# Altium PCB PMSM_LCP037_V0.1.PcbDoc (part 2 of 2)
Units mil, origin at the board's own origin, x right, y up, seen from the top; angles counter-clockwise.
Board outline 6102.36 x 5157.48 mil, 2 copper layers (Top Layer, Bottom Layer); 106 components, 56 nets, 276 pads, 861 vias.
Unrouted connection lines stored in the file: 2.
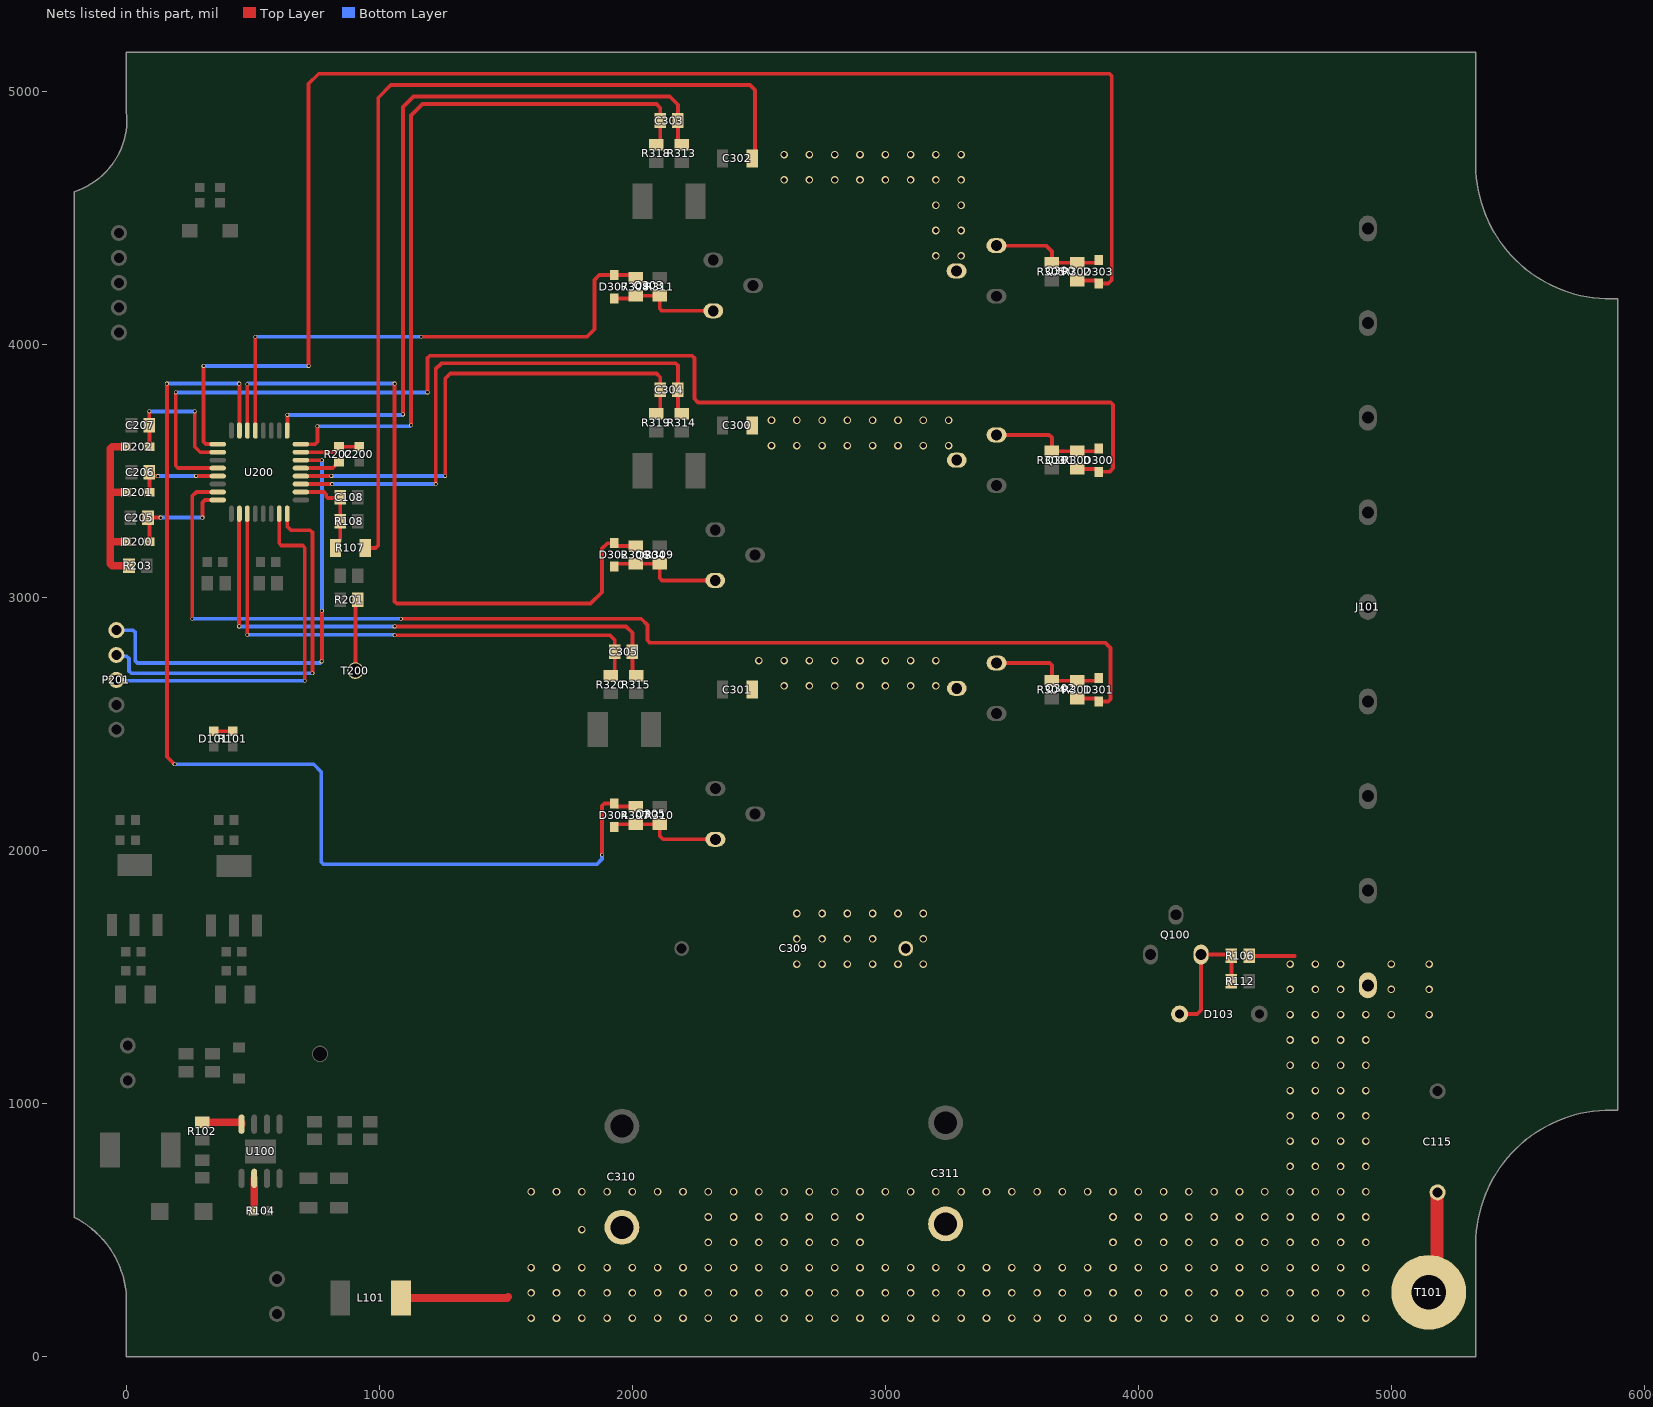
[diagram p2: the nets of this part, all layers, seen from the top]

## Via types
v1: diameter 30, hole 20, Top Layer to Bottom Layer, 742 vias
v2: diameter 15, hole 10, Top Layer to Bottom Layer, 100 vias
v3: diameter 30, hole 15, Top Layer to Bottom Layer, 14 vias
v4: diameter 24, hole 12, Top Layer to Bottom Layer, 4 vias
v5: diameter 20, hole 10, Top Layer to Bottom Layer, 1 vias

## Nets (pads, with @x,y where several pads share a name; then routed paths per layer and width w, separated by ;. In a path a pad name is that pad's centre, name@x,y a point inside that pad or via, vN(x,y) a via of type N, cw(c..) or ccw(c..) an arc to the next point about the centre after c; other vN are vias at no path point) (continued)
NetC200_2: C200.2 R202.1 U200.15 | length 239.6
  Top Layer w15: U200.15@689.37,3573.74 817.44,3573.74 839.02,3595.31 R202.1@840,3595.31 C200.2@920,3595.32
NetD101_A: D101.A R101.1 | length 75
  Top Layer w15: D101.A@345,2470.32 R101.1@420,2470.31
NetD103_2: D103.2 Q100.1 R106.1 R112.2 | length 530.3
  Top Layer w15: D103.2@4163.35,1352.52 4233.31,1352.52 4248.31,1367.52 Q100.1@4248.31,1587.52 4358.31,1587.52 R106.1@4363.31,1592.52 ; R106.1@4368.27,1582.52 4368.27,1487.56 R112.2@4373.31,1482.52
NetD200_1: D200.1 D201.1 D202.1 R203.2 | length 731.8
  Top Layer w30: D201.1@-1.57,3415 -57.5,3415 -65,3407.5 ; D202.1@-1.57,3595 -56.21,3595 -65,3586.21 -65,3407.5 ; D200.1@-1.46,3220 -56.21,3220 -65,3228.79 ; R203.2@9.96,3125 -56.21,3125 -65,3133.79 -65,3228.79 ; -65,3228.79 -65,3407.5
NetD300_1: D300.1 Q301.1 R300.2 R303.2 | length 467.9
  Top Layer w15: Q301.1@3439.8,3642.2 3647.32,3642.2 3658.31,3631.21 R303.2@3658.31,3577.56 R300.2@3758.31,3577.6 R300.2@3758.31,3577.6 3834.47,3577.6 3843.31,3586.44 D300.1@3843.31,3588.98
NetD301_1: D301.1 Q302.1 R301.2 R304.2 | length 474.7
  Top Layer w15: Q302.1@3439.8,2740.24 3440.04,2740 3649.52,2740 3658.31,2731.21 R304.2@3658.31,2670.04 R301.2@3758.31,2670.04 3834.47,2670.04 3843.31,2678.88 D301.1@3843.31,2681.46
NetD302_1: D302.1 Q304.1 R306.2 R309.2 | length 465.9
  Top Layer w15: D302.1@1928.31,3121.06 1928.31,3123.64 1937.15,3132.48 R306.2@2013.31,3132.48 R309.2@2108.31,3132.48 2108.31,3075.79 2117.09,3067.01 Q304.1@2327.6,3067.01
NetD303_1: D303.1 Q300.1 R302.2 R305.2 | length 464.4
  Top Layer w15: Q300.1@3439.02,4390.24 3634.76,4390.24 3658.31,4366.69 R305.2@3658.31,4322.56 R302.2@3758.31,4322.56 3834.47,4322.56 3843.31,4331.4 D303.1@3843.31,4333.98
NetD304_1: D304.1 Q305.1 R307.2 R310.2 | length 457.2
  Top Layer w15: D304.1@1928.31,2091.06 1928.31,2093.64 1937.15,2102.48 R307.2@2013.31,2102.48 R310.2@2108.31,2102.48 2108.31,2056.69 2121.61,2043.39 Q305.1@2327.99,2043.39
NetD307_1: D307.1 Q303.1 R308.2 R311.2 | length 459.3
  Top Layer w15: D307.1@1923.31,4192.52 1934.76,4181.06 2001.89,4181.06 R308.2@2013.31,4192.48 R308.2@2013.31,4192.48 R311.2@2108.31,4192.48 2108.31,4141.31 2117.09,4132.52 Q303.1@2318.31,4132.52
NetR102_2: R102.2 U100.8 | length 161.1
  Top Layer w30: R102.2@300,925.04 451.85,925.04 455,921.89 U100.8@455,917.11
NetR104_1: R104.1 U100.2 | length 130.1
  Top Layer w30: R104.1@499.69,575 499.69,575.98 505,581.3 U100.2@505,702.89
NetR201_1: R201.1 T200.1 | length 284.2
  Top Layer w15: T200.1@905,2710 905,2979.96 R201.1@915.04,2990
NetR202_2: R202.2 U200.13 | length 160.5
  Top Layer w15: U200.13@689.37,3510.75 815.08,3510.75 839.02,3534.68 R202.2@840,3534.68
OPA0N: C303.1 R318.1 U200.16 | length 2888.3
  Top Layer w15: U200.16@689.37,3605.24 745,3605.24 755,3615.24 v2(755,3676.21) ; v2(1125,3680) 1125,4905 1170,4950 2095,4950 2109.96,4935.04 C303.1@2109.96,4885 2109.96,4805 R318.1@2095,4790.04
  Bottom Layer w15: v2(755,3676.21) 1121.21,3676.21 v2(1125,3680)
OPA0P: C303.2 R313.1 U200.17 | length 3016.3
  Top Layer w15: U200.17@635.24,3659.37 635.98,3660.12 v2(635.98,3720.98) ; v2(1092.99,3722.99) 1092.99,4937.99 1135,4980 2147.42,4980 2180.04,4947.38 C303.2@2180.04,4885 2180.04,4805 R313.1@2195,4790.04
  Bottom Layer w15: v2(635.98,3720.98) 1090.98,3720.98 v2(1092.99,3722.99)
OPA1N: C305.1 R320.1 U200.3 | length 2086.7
  Top Layer w15: U200.3@477.76,3330.63 477.76,2852.24 v2(478.32,2851.68) ; v2(1060,2850) 1911.17,2850 1929.96,2831.21 C305.1@1929.96,2785 1929.96,2705 R320.1@1915,2690.04
  Bottom Layer w15: v2(478.32,2851.68) 1058.32,2851.68 v2(1060,2850)
OPA1P: C305.2 R315.1 U200.2 | length 2187.7
  Top Layer w15: v2(445,2885) 445,3329.37 U200.2@446.26,3330.63 ; v2(1060,2885) 1975,2885 2000.04,2859.96 C305.2@2000.04,2785 2000.04,2705 R315.1@2015,2690.04
  Bottom Layer w15: v2(445,2885) v2(1060,2885)
OPA2N: C304.1 R319.1 U200.12 | length 1971.3
  Top Layer w15: U200.12@689.37,3479.25 v2@810,3479.25 ; v2(1260,3480) 1260,3865 1280,3885 2095,3885 2109.96,3870.04 C304.1@2109.96,3820 2109.96,3740 R319.1@2095,3725.04
  Bottom Layer w15: v2(810,3480) v2(1260,3480)
OPA2P: C304.2 R314.1 U200.11 | length 2155.6
  Top Layer w15: U200.11@689.37,3447.76 v2(812.76,3447.76) ; v2(1222.24,3447.76) 1222.24,3902.24 1245,3925 2171.25,3925 2180.04,3916.21 C304.2@2180.04,3820 2180.04,3740 R314.1@2195,3725.04
  Bottom Layer w15: v2(812.76,3447.76) v2(1222.24,3447.76)
PA0-DIO: P201.3 U200.7 | length 1498
  Top Layer w15: U200.7@603.74,3330.63 603.74,3213.79 612.53,3205 696.21,3205 705,3196.21 v2(705,2670)
  Bottom Layer w15: P201.3@-40,2673.43 -36.57,2670 v2(705,2670)
PA1-CLK: P201.2 U200.8 | length 1550.1
  Top Layer w15: U200.8@635.24,3330.63 635.24,3279.76 650,3265 726.21,3265 735,3256.21 v2(735,2700)
  Bottom Layer w15: P201.2@-40,2771.85 -34.85,2766.7 1.21,2766.7 10,2757.92 10,2708.79 18.79,2700 v2(735,2700)
PB0-STB: P201.1 U200.14 | length 1815.6
  Top Layer w15: U200.14@689.37,3542.24 v2(772.76,3542.24) ; v2@770,2745 v2(771.38,2746.38) 772.76,2747.76 v2(772.76,2947.24)
  Bottom Layer w15: P201.1@-40,2870.28 -39.72,2870 26.21,2870 35,2861.21 35,2748.79 43.79,2740 765,2740 v2(771.38,2746.38) ; v2(772.76,2947.24) v2(772.76,3542.24)
PE: C115.2 T101.6 | length 409.5
  Top Layer w50: T101.6@5148.31,252.52 5180.82,285.03 5180.82,645.03 C115.2@5183.31,647.52
POWER: C300.2 C301.2 C302.2 C309.2 C310.1 C311.1 J101.1 L101.1 Q300.2 Q301.2 Q302.2 R106.2 R107.2 | length 4226.2
  Top Layer w15: R107.2@943.66,3195 985,3195 995,3205 995,4975 1045,5025 2465,5025 2485,5005 2485,4746.34 C302.2@2473.66,4735 ; R106.2@4438.35,1582.52 4618.31,1582.52
  Top Layer w30: L101.1@1085,230 1505,230 1510,235
  other v1: 1600,150 1700,150 1800,150 1900,150 2000,150 2100,150 2200,150 2300,150 2400,150 2500,150 2600,150 2700,150 2800,150 2900,150 3000,150 3100,150 3200,150 3300,150 3400,150 3500,150 3600,150 3700,150 3800,150 3900,150 4000,150 4100,150 4200,150 4300,150 4400,150 4500,150 4600,150 4700,150 4800,150 4900,150 1600,250 1700,250 1800,250 1900,250 2000,250 2100,250 2200,250 2300,250 2400,250 2500,250 2600,250 2700,250 2800,250 2900,250 3000,250 3100,250 3200,250 3300,250 3400,250 3500,250 3600,250 3700,250 3800,250 3900,250 4000,250 4100,250 4200,250 4300,250 4400,250 4500,250 4600,250 4700,250 4800,250 4900,250 1600,350 1700,350 1800,350 1900,350 2000,350 2100,350 2200,350 2300,350 2400,350 2500,350 2600,350 2700,350 2800,350 2900,350 3000,350 3100,350 3200,350 3300,350 3400,350 3500,350 3600,350 3700,350 3800,350 3900,350 4000,350 4100,350 4200,350 4300,350 4400,350 4500,350 4600,350 4700,350 4800,350 4900,350 2300,450 2400,450 2500,450 2600,450 2700,450 2800,450 2900,450 3900,450 4000,450 4100,450 4200,450 4300,450 4400,450 4500,450 4600,450 4700,450 4800,450 4900,450 1800,500 2300,550 2400,550 2500,550 2600,550 2700,550 2800,550 2900,550 3900,550 4000,550 4100,550 4200,550 4300,550 4400,550 4500,550 4600,550 4700,550 4800,550 4900,550 1600,650 1700,650 1800,650 1900,650 2000,650 2100,650 2200,650 2300,650 2400,650 2500,650 2600,650 2700,650 2800,650 2900,650 3000,650 3100,650 3200,650 3300,650 3400,650 3500,650 3600,650 3700,650 3800,650 3900,650 4000,650 4100,650 4200,650 4300,650 4400,650 4500,650 4600,650 4700,650 4800,650 4900,650 4600,750 4700,750 4800,750 4900,750 4600,850 4700,850 4800,850 4900,850 4600,950 4700,950 4800,950 4900,950 4600,1050 4700,1050 4800,1050 4900,1050 4600,1150 4700,1150 4800,1150 4900,1150 4600,1250 4700,1250 4800,1250 4900,1250 4600,1350 4700,1350 4800,1350 4900,1350 5000,1350 5150,1350 4600,1450 4700,1450 4800,1450 5000,1450 5150,1450 2650,1550 2750,1550 2850,1550 2950,1550 3050,1550 3150,1550 4600,1550 4700,1550 4800,1550 5000,1550 5150,1550 2650,1650 2750,1650 2850,1650 2950,1650 3150,1650 2650,1750 2750,1750 2850,1750 2950,1750 3050,1750 3150,1750 2600,2650 2700,2650 2800,2650 2900,2650 3000,2650 3100,2650 3200,2650 2500,2750 2600,2750 2700,2750 2800,2750 2900,2750 3000,2750 3100,2750 3200,2750 2550,3600 2650,3600 2750,3600 2850,3600 2950,3600 3050,3600 3150,3600 3250,3600 2550,3700 2650,3700 2750,3700 2850,3700 2950,3700 3050,3700 3150,3700 3250,3700 3200,4350 3300,4350 3200,4450 3300,4450 3200,4550 3300,4550 2600,4650 2700,4650 2800,4650 2900,4650 3000,4650 3100,4650 3200,4650 3300,4650 2600,4750 2700,4750 2800,4750 2900,4750 3000,4750 3100,4750 3200,4750 3300,4750
UH: D303.2 R302.1 U200.25 | length 6039.8
  Top Layer w15: v2(305,3915) 305,3615 314.02,3605.98 359.88,3605.98 U200.25@360.63,3605.24 ; v2(720,3915) 720,5030 760,5070 3886.21,5070 3895,5061.21 3895,4255 3881.06,4241.06 D303.2@3843.31,4241.06 3843.31,4243.64 3834.47,4252.48 R302.1@3758.31,4252.48
  Bottom Layer w15: v2(305,3915) v2(720,3915)
UL: D307.2 R308.1 U200.21 | length 2088.2
  Top Layer w15: U200.21@509.25,3659.37 v2(509.25,4030) ; v2(1165,4030) 1820,4030 1850,4060 1850,4255 1868.98,4273.98 D307.2@1928.31,4273.98 ; D307.2@1934.76,4273.98 2001.89,4273.98 R308.1@2013.31,4262.56
  Bottom Layer w15: v2(509.25,4030) v2(1165,4030)
VB-U: C205.2 D200.2 U200.32 | length 437.2
  Top Layer w15: D200.2@91.46,3220 91.46,3308.58 C205.2@85.04,3315 v2(135,3315) ; v2(300,3315) 300,3374.76 310,3384.76 U200.32@360.63,3384.76
  Bottom Layer w15: v2(135,3315) v2(300,3315)
VB-V: C206.2 D201.2 U200.29 | length 356
  Top Layer w15: C206.2@89.92,3495 91.34,3493.58 C206.2@91.34,3493.17 ; D201.2@91.34,3415 C206.2@91.34,3493.17 ; v2(124.57,3479.25) 105.26,3479.25 C206.2@91.34,3493.17 ; v2@275,3479.25 U200.29@360.63,3479.25
  Bottom Layer w15: v2(124.57,3479.25) 274.25,3479.25 v2(275,3480)
VB-W: C207.2 D202.2 U200.26 | length 560.1
  Top Layer w15: v2(90,3735) 89.92,3734.92 C207.2@89.92,3680 91.34,3678.58 D202.2@91.34,3595 ; v2(270,3735) 270,3595 291.26,3573.74 U200.26@360.63,3573.74
  Bottom Layer w15: v2(90,3735) v2(270,3735)
Vdect: C108.2 R107.1 R108.2 U200.10 | length 379.1
  Top Layer w15: U200.10@689.37,3416.26 781.21,3416.26 790,3407.47 790,3398.79 796.14,3392.64 842.61,3392.64 C108.2@844.96,3395 R108.2@844.96,3300 844.96,3226.81 826.34,3208.19 R107.1@826.34,3195
VH: D300.2 R300.1 U200.28 | length 4884
  Top Layer w15: v2(195,3810) 195,3520 204.25,3510.75 U200.28@360.63,3510.75 ; v2(1190,3810) 1190,3946.21 1198.79,3955 2236.21,3955 2245,3946.21 2245,3785 2260,3770 3891.21,3770 3900,3761.21 3900,3510 3886.06,3496.06 D300.2@3843.31,3496.06 3843.31,3498.68 3834.47,3507.52 R300.1@3758.31,3507.52
  Bottom Layer w15: v2(195,3810) v2(1190,3810)
VL: D302.2 R306.1 U200.22 | length 2790.9
  Top Layer w15: U200.22@477.76,3659.37 v2(477.76,3842.24) ; v2(1060,3845) 1060,2983.79 1068.79,2975 1835,2975 1880,3020 1880,3192.83 1901.14,3213.98 D302.2@1928.31,3213.98 1928.31,3211.4 1937.15,3202.56 R306.1@2013.31,3202.56
  Bottom Layer w15: v2(477.76,3842.24) 480.51,3845 v2(1060,3845)
WH: D301.2 R301.1 U200.31 | length 4649.4
  Top Layer w15: v2(260,2915) 260,3400 276.26,3416.26 U200.31@360.63,3416.26 ; v2(1085,2915) 2035,2915 2060,2890 2060,2830 2070,2820 3870,2820 3890,2800 3890,2597.33 3881.21,2588.54 D301.2@3843.31,2588.54 3843.31,2591.12 3834.47,2599.96 R301.1@3758.31,2599.96
  Bottom Layer w15: v2(260,2915) v2(1085,2915)
WL: D304.2 R307.1 U200.23 | length 4413.4
  Top Layer w15: v2(160,3845) 160,2370 v2(190,2340) ; U200.23@446.26,3659.37 v2@446.26,3845 ; v2(1880,1982.28) 1880,2176.21 1888.79,2185 1927.28,2185 D304.2@1928.31,2183.98 1928.31,2181.4 1937.15,2172.56 R307.1@2013.31,2172.56
  Bottom Layer w15: v2(160,3845) v2(445,3845) ; v2(190,2340) 740,2340 770,2310 770,1953.79 778.79,1945 1860,1945 1880,1965 v2(1880,1982.28)
pads on no net: J101.6 J101.7 J101.8 J101.9 Q300. Q301. Q302. Q303. Q304. Q305. U100.6 U100.7 U100.9
copper on no net:
  other v4: 510.32,790.31 549.69,790.31 510.32,829.68 549.69,829.68

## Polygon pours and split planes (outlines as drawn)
POWER on Top Layer "POWER_L01_P109" (solid, remove dead copper, pour order 109): 3190,1775 3200,1765 3200,1470 3170,1440 2575,1440 2550,1465 2550,1760 2565,1775
DGND on Top Layer "DGND_L01_P108" (solid, remove dead copper, pour order 108): 1070,2805 1830,2805 1850,2785 1850,2645 1855,2640 1945,2640 1955,2630 1955,2250 1935,2230 1130,2230 1060,2300 1060,2795
DGND on Top Layer "DGND_L01_P107" (solid, remove dead copper, pour order 107): 1941.46,2578.54 1940,2580 1870,2580 1845,2605 1845,2790 1070,2805 1005,2735 1005,2640 955,2590 830,2590 810,2570 810,1245 825,1230 825,1090 835,1080 990,1080 1125,945 1125,865 1180,810 3680,810 3725,855 3725,1115 3915,1305 4095,1305 4110,1320 4110,1390 4135,1415 4170,1415 4195,1440 4195,1640 4180,1655 4045,1655 4030,1670 4030,1780 4010,1800 3260,1800 3235,1775 3235,1450 3170,1385 2555,1385 2520,1420 2520,1750 2470,1800 1865,1800 1835,1830 1835,2220 1845,2230 1935,2230 1950,2245 1950,2570 1940,2580 1870,2580 1845,2605 1845,2790 1830,2790 1070,2800
DGND on Top Layer "DGND_L01_P105" (solid, remove dead copper, pour order 105): 4151.33,1649.5 4035.5,1649.5 4015,1670 4015,1775 4000,1790 3260,1790 3255,1785 3255,1444.21 3198.31,1387.52 977.52,1387.52 945,1355 945,1125 1262.48,807.52 3643.31,807.52 3688.31,852.52 3688.31,1073.31 3917.52,1302.52 4107.52,1302.52 4110,1305 4110,1390 4135,1415 4170,1415 4190,1435 4190,1640 4180,1650 4151.83,1650
POWER on Top Layer "POWER_L01_P088" (solid, remove dead copper, pour order 88): 2435,2760 2435,2585 2475.46,2544.54 3319.51,2544.54 3330,2555.03 3330,2775 3315,2790 2465,2790
ISENCE on Top Layer "ISENCE_L01_P087" (solid, remove dead copper, pour order 87): 2400,2550 2400,2725 2385,2740 2110,2740 2080,2710 2080,2525 2375,2525
POWER on Top Layer "POWER_L01_P086" (solid, remove dead copper, pour order 86): 2440,3585 2460,3565 3185,3565 3205,3545 3205,3505 3225,3485 3330,3485 3355,3510 3355,3725 3340,3740 2445,3740 2440,3735
IV on Top Layer "IV_L01_P085" (solid, remove dead copper, pour order 85): 2417.87,3594.25 2417.87,3737.13 2405,3750 2260,3750 2255,3745 2255,3600 2265,3590 2413.62,3590
POWER on Top Layer "POWER_L01_P084" (solid, remove dead copper, pour order 84): 2440,4795 2455,4810 3345,4810 3375,4780 3375,4275 3350,4250 3180,4250 3150,4280 3150,4545 3091.18,4603.82 2466.18,4603.82 2440,4630
IU on Top Layer "IU_L01_P083" (solid, remove dead copper, pour order 83): 2410,4660 2410,4805 2405,4810 2270,4810 2265,4805 2265,4670 2275,4660
DGND on Top Layer "DGND_L01_P081" (solid, remove dead copper, pour order 81): 990,4700 1020,4670 1020,2795 980,2755 800,2755 770,2725 770,2010 735,1975 220,1975 110,2085 110,2965 60,3015 -105,3015 -150,3060 -150,4545 5,4700
DGND on Top Layer "DGND_L01_P079" (solid, remove dead copper, pour order 79): 970,1000 1050,920 1050,85 1015,50 440,50 420,70 420,415 350,485 40,485 -130,655 -130,975 -105,1000
no net on Top Layer "NONET_L01_P072" (solid, pour order 72): 1170,2990
ISENCE on Top Layer "ISENCE_L01_P069" (solid, remove dead copper, pour order 69): 1325,3690 2130,3690 2160,3660 2160,3305 2150,3295 2100,3295 2090,3285 2090,3260 2075,3245 1320,3245 1300,3265 1300,3665
ISENCE on Top Layer "ISENCE_L01_P067" (solid, remove dead copper, pour order 67): 1345,4755 2150,4755 2160,4745 2160,4370 2150,4360 2100,4360 2090,4350 2090,4325 2070,4305 1345,4305 1300,4350 1300,4710
ISENCE on Top Layer "ISENCE_L01_P066" (solid, remove dead copper, pour order 66): 2390,2560 2400,2550 2400,2135 2385,2120 2185,2120 2160,2145 2160,2280 2150,2290 2000,2290 1985,2305 1985,2550 1995,2560
IV on Top Layer "IV_L01_P065" (solid, remove dead copper, pour order 65): 2187.87,3594.25 2202.87,3609.25 2390.75,3609.25 2400,3600 2400,3200 2359.25,3159.25 2217.87,3159.25 2187.87,3189.25
DGND on Top Layer "DGND_L01_P064" (solid, remove dead copper, pour order 64): 980,1800 980,1195 2510,1195 2510,1760 2470,1800
MOTOR-C on Top Layer "MOTOR-C_L01_P062" (solid, remove dead copper, pour order 62): 2435,2465 2460,2490 3310,2490 3350,2530 3350,2595 3385,2630 3585,2630 3600,2615 3600,2450.51 3630.51,2420 3975,2420 4030,2365 5170,2365 5230,2305 5230,2095 5190,2055 4000,2055 3960,2015 3960,1840 2465,1840 2435,1870
MOTOR-B on Top Layer "MOTOR-B_L01_P061" (solid, remove dead copper, pour order 61): 2435,3450 2450,3465 3350,3465 3380,3495 3380,3570 3390,3580 3575,3580 3590,3565 3590,3420 3620,3390 3995,3390 4590,2795 5165,2795 5225,2735 5225,2440 5200,2415 4040,2415 3960,2495 3960,2785 3880,2865 2475,2865 2435,2905
MOTOR-A on Top Layer "MOTOR-A_L01_P060" (solid, remove dead copper, pour order 60): 2425,4500 2453.4,4528.4 3031.6,4528.4 3090,4470 3090,4225 3105,4210 3380,4210 3395,4225 3395,4295 3405,4305 3580,4305 3595,4290 4545,4290 4795,4040 4795,3230 5190,3230 5225,3195 5225,2915 5140,2830 4730,2830 4065,3495 4065,3740 3995,3810 2475,3810 2425,3860
IU on Top Layer "IU_L01_P059" (solid, remove dead copper, pour order 59): 2180,4660 2195,4675 2395,4675 2410,4660 2410,4235 2400,4225 2210,4225 2180,4255
no net on Top Layer "NONET_L01_P058" (solid, pour order 58): 2443.31,4417.52
GND on Top Layer "GND_L01_P053" (solid, remove dead copper, pour order 53): 5198.31,1672.52 5228.31,1702.52 5228.31,1987.52 5193.31,2022.52 4063.31,2022.52 4043.31,2002.52 4043.31,1692.52 4063.31,1672.52
POWER on Top Layer "POWER_L01_P052" (solid, remove dead copper, pour order 52): 4597.52,1647.52 4573.31,1623.31 4573.31,1232.52 3932.52,1232.52 3783.31,1083.31 3783.31,812.52 3778.31,812.52 3718.31,752.52 1543.31,752.52 1483.31,692.52 1483.31,67.52 1508.31,42.52 4863.31,42.52 4918.31,97.52 4918.31,382.52 5098.31,562.52 5098.31,1162.52 5203.31,1162.52 5223.31,1182.52 5223.31,1597.52 5228.31,1602.52 5183.31,1647.52
no net on Top Layer "NONET_L01_P048" (solid, pour order 48): 2853.31,4502.52
POWER on Top Layer "POWER_L01_P028" (solid, pour order 28): 4903.31,1457.52
no net on Top Layer "NONET_L01_P024" (solid, pour order 24): 2283.31,4582.52
MOTOR-C on Bottom Layer "MOTOR-C_L02_P101" (solid, remove dead copper, pour order 101): 2435,1870 2465,1840 2580,1840 2615,1875 2615,2470 2595,2490 2460,2490 2435,2465
MOTOR-B on Bottom Layer "MOTOR-B_L02_P100" (solid, remove dead copper, pour order 100): 2450,3465 2435,3450 2435,2905 2475,2865 2595,2865 2615,2885 2615,3450 2600,3465
MOTOR-A on Bottom Layer "MOTOR-A_L02_P099" (solid, remove dead copper, pour order 99): 2425,4500 2425,3830 2445,3810 2570,3810 2600,3840 2600,4505 2575,4530 2455,4530
POWER on Bottom Layer "POWER_L02_P098" (solid, remove dead copper, pour order 98): 2440,4795 2455,4810 3345,4810 3375,4780 3375,4275 3350,4250 3180,4250 3150,4280 3150,4545 3091.18,4603.82 2466.18,4603.82 2440,4630
POWER on Bottom Layer "POWER_L02_P097" (solid, remove dead copper, pour order 97): 2440,3585 2460,3565 3185,3565 3205,3545 3205,3505 3225,3485 3330,3485 3355,3510 3355,3725 3340,3740 2445,3740 2440,3735
POWER on Bottom Layer "POWER_L02_P096" (solid, remove dead copper, pour order 96): 2435,2760 2435,2585 2475.46,2544.54 3319.51,2544.54 3330,2555.03 3330,2775 3315,2790 2465,2790
GND on Bottom Layer "GND_L02_P095" (solid, remove dead copper, pour order 95): 4063.31,2022.52 4043.31,2002.52 4043.31,1816.69 4055,1805 4110,1805 4120,1795 4120,1690 4135,1675 5200.79,1675 5228.31,1702.52 5228.31,1987.52 5193.31,2022.52
MOTOR-C on Bottom Layer "MOTOR-C_L02_P094" (solid, remove dead copper, pour order 94): 3385,1865 3410,1840 3945,1840 3960,1855 3960,2015 4000,2055 5190,2055 5230,2095 5230,2310 5175,2365 4030,2365 3975,2420 3895,2420 3843.31,2471.69 3843.31,2629.88 3399.88,2629.88 3385,2615
MOTOR-B on Bottom Layer "MOTOR-B_L02_P093" (solid, remove dead copper, pour order 93): 3390,3580 3380,3570 3380,2815 3390,2805 3905,2805 3940,2770 3940,2490 4015,2415 5200,2415 5230,2445 5230,2730 5165,2795 4635,2795 3995,3435 3995,3545 3960,3580
MOTOR-A on Bottom Layer "MOTOR-A_L02_P092" (solid, remove dead copper, pour order 92): 3395,4295 3395,4225 3380,4210 3380,3750 3410,3720 4058.86,3720 4080,3698.86 4080,3482.72 4723.86,2838.86 5143.86,2838.86 5230,2925 5230,3185 5190,3225 5190,3230 4875,3230 4795,3310 4795,4040 4530,4305 3405,4305
DGND on Bottom Layer "DGND_L02_P091" (solid, remove dead copper, pour order 91): 3040,810 3040,1160 3060,1180 3095,1180 3400,1485 3400,1750 3440,1790 4075,1790 4085,1780 4085,1665 4100.5,1649.5 4151.33,1649.5 4163.31,1637.52 4163.31,1447.52 4018.31,1302.52 3772.52,1302.52 3740,1270 3740,861.59 3675.14,796.73 3053.27,796.73
DGND on Bottom Layer "DGND_L02_P090" (solid, remove dead copper, pour order 90): 1080,1800 1050,1770 1050,1100 1342.48,807.52 2242.52,807.52 2290,855 2290,1760 2250,1800
DGND on Bottom Layer "DGND_L02_P082" (solid, remove dead copper, pour order 82): 990,4700 1020,4670 1020,2795 980,2755 800,2755 770,2725 770,2010 735,1975 220,1975 110,2085 110,2965 60,3015 -105,3015 -150,3060 -150,4545 5,4700
DGND on Bottom Layer "DGND_L02_P080" (solid, remove dead copper, pour order 80): 1075,1000 1185,890 1185,150 1085,50 440,50 420,70 420,415 350,485 40,485 -130,655 -130,975 -105,1000
ISENCE on Bottom Layer "ISENCE_L02_P078" (solid, remove dead copper, pour order 78): 2390,2560 2400,2550 2400,2135 2385,2120 2060,2120 2060,2290 2000,2290 1985,2305 1985,2550 1995,2560
IV on Bottom Layer "IV_L02_P077" (solid, remove dead copper, pour order 77): 2186.87,3595.26 2201.87,3610.26 2389.74,3610.26 2400,3600 2400,3200 2360.26,3160.26 2216.87,3160.26 2186.87,3190.26
IU on Bottom Layer "IU_L02_P076" (solid, remove dead copper, pour order 76): 2180,4660 2195,4675 2395,4675 2410,4660 2410,4235 2400,4225 2210,4225 2180,4255
ISENCE on Bottom Layer "ISENCE_L02_P063" (solid, remove dead copper, pour order 63): 2125,4755 2125,2180 2066.77,2121.77 1353.23,2121.77 1300,2175 1300,4710 1345,4755
POWER on Bottom Layer "POWER_L02_P057" (solid, remove dead copper, pour order 57): 2328.31,722.52 2328.31,1682.52 2428.31,1782.52 2630,1782.52 2630,4715 2730,4815 3310,4815 3358.31,4766.69 3358.31,1488.31 3065,1195 2985,1195 2985,722.52
no net on Bottom Layer "NONET_L02_P056" (solid, pour order 56): 2233.31,727.52
POWER on Bottom Layer "POWER_L02_P055" (solid, remove dead copper, pour order 55): 4616.54,1648.39 4586.54,1618.39 4586.54,1248.39 4571.54,1233.39 3831.54,1233.39 3781.54,1183.39 3781.54,813.39 3776.54,813.39 3716.54,753.39 1541.54,753.39 1481.54,693.39 1481.54,68.39 1506.54,43.39 4861.54,43.39 4916.54,98.39 4916.54,383.39 5061.54,528.39 5061.54,1128.39 5096.54,1163.39 5201.54,1163.39 5221.54,1183.39 5221.54,1598.39 5226.54,1603.39 5181.54,1648.39
DGND on Bottom Layer "DGND_L02_P043" (solid, pour order 43): 1248.31,2722.52
DGND on Bottom Layer "DGND_L02_P033" (solid, pour order 33): 4538.31,2597.52

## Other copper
Top Layer:
  pour cut-out: 3974.96,922.52 ccw(c4148.31,922.52) 4148.31,749.17 ccw(c4148.31,922.52) 4321.66,922.52 ccw(c4148.31,922.52) 4148.31,1095.87 ccw(c4148.31,922.52)
  pour cut-out: 1490.04,2143.19 ccw(c1663.39,2143.19) 1663.39,1969.84 ccw(c1663.39,2143.19) 1836.74,2143.19 ccw(c1663.39,2143.19) 1663.39,2316.54 ccw(c1663.39,2143.19)
  pour cut-out: 1490.04,3166.81 ccw(c1663.39,3166.81) 1663.39,2993.46 ccw(c1663.39,3166.81) 1836.74,3166.81 ccw(c1663.39,3166.81) 1663.39,3340.16 ccw(c1663.39,3166.81)
  pour cut-out: 1482.16,4233.74 ccw(c1655.51,4233.74) 1655.51,4060.39 ccw(c1655.51,4233.74) 1828.86,4233.74 ccw(c1655.51,4233.74) 1655.51,4407.09 ccw(c1655.51,4233.74)
  pour cut-out: 3930.98,4288.86 ccw(c4104.33,4288.86) 4104.33,4115.51 ccw(c4104.33,4288.86) 4277.68,4288.86 ccw(c4104.33,4288.86) 4104.33,4462.21 ccw(c4104.33,4288.86)
  pour cut-out: 3930.98,3540.83 ccw(c4104.33,3540.83) 4104.33,3367.48 ccw(c4104.33,3540.83) 4277.68,3540.83 ccw(c4104.33,3540.83) 4104.33,3714.18 ccw(c4104.33,3540.83)
  pour cut-out: 3930.98,2639.25 ccw(c4104.33,2639.25) 4104.33,2465.9 ccw(c4104.33,2639.25) 4277.68,2639.25 ccw(c4104.33,2639.25) 4104.33,2812.6 ccw(c4104.33,2639.25)
Bottom Layer:
  pour cut-out: 1489.96,2147.52 ccw(c1663.31,2147.52) 1663.31,1974.17 ccw(c1663.31,2147.52) 1836.66,2147.52 ccw(c1663.31,2147.52) 1663.31,2320.87 ccw(c1663.31,2147.52)
  pour cut-out: 1489.96,3167.52 ccw(c1663.31,3167.52) 1663.31,2994.17 ccw(c1663.31,3167.52) 1836.66,3167.52 ccw(c1663.31,3167.52) 1663.31,3340.87 ccw(c1663.31,3167.52)
  pour cut-out: 1484.96,4232.52 ccw(c1658.31,4232.52) 1658.31,4059.17 ccw(c1658.31,4232.52) 1831.66,4232.52 ccw(c1658.31,4232.52) 1658.31,4405.87 ccw(c1658.31,4232.52)
  pour cut-out: 3930.95,4288.73 ccw(c4104.3,4288.73) 4104.3,4115.38 ccw(c4104.3,4288.73) 4277.65,4288.73 ccw(c4104.3,4288.73) 4104.3,4462.08 ccw(c4104.3,4288.73)
  pour cut-out: 3929.96,3542.52 ccw(c4103.31,3542.52) 4103.31,3369.17 ccw(c4103.31,3542.52) 4276.66,3542.52 ccw(c4103.31,3542.52) 4103.31,3715.87 ccw(c4103.31,3542.52)
  pour cut-out: 3929.96,2637.52 ccw(c4103.31,2637.52) 4103.31,2464.17 ccw(c4103.31,2637.52) 4276.66,2637.52 ccw(c4103.31,2637.52) 4103.31,2810.87 ccw(c4103.31,2637.52)
  pour cut-out: 3974.96,922.52 ccw(c4148.31,922.52) 4148.31,749.17 ccw(c4148.31,922.52) 4321.66,922.52 ccw(c4148.31,922.52) 4148.31,1095.87 ccw(c4148.31,922.52)

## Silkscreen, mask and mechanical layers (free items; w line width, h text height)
Top Overlay:
  circle w10: c187.01,4899.09 r157.48
  circle w10: c5147.64,4899.09 r157.48
  circle w10: c187.01,253.43 r157.48
  circle w10: c5147.64,253.43 r157.48
  lines w10: 1662.05,4229.61 1662.05,4230 ; 1662.44,3167.01 1662.83,3167.01 ; 1662.83,2143.39 1663.23,2143.39
  text "光伏水泵控制LCP037" at 2788.31,4921.68 h150
  text "2023-5-9-V0.1" at 2799.89,4801.33 h120
  text "DG" at 150,4120.89 h80
  text "5V" at 150,4010.89 h80
  text "下载口" at -100,3866.96 h80
  text "U" at 5273.62,2885.57 h200
  text "STB" at 106.64,2848.41 h80
  text "CLK" at 106.64,2748.16 h80
  text "DIO" at 106.64,2648.49 h80
  text "GD" at 106.64,2548.49 h80
  text "V" at 5269.87,2489.65 h200
  text "5V" at 106.64,2448.49 h80
  text "5V指示" at 280,2286.73 h80
  text "W" at 5253.94,2131.38 h200
  text "-" at 5293.31,1746.84 h300
  text "+" at 5281.5,1398.05 h200
  text "12V" at 700,1095 h80
  text "外壳" at 5088.67,25.37 h90
Mechanical 1:
  circle w10: c4104.57,2640.24 r157.48
  circle w10: c4143.7,922.72 r157.48
  circle w10: c4103.78,3542.2 r157.48
  circle w10: c4103.78,4288.86 r157.48
  circle w10: c1662.83,2143.39 r157.48
  circle w10: c1662.83,3167.01 r157.48
  circle w10: c1662.83,4230 r157.48
  circle w10: c187.72,252.99 r68.9
  circle w10: c187.72,4897.68 r68.9
  circle w10: c5147.64,4899.09 r68.9
  pour cut-out: 4104.57,2482.76 cw(c4104.57,2640.24) 3947.09,2640.24 cw(c4104.57,2640.24) 4104.57,2797.72 cw(c4104.57,2640.24) 4262.05,2640.24 cw(c4104.57,2640.24)
  lines w10: -206.69,548.7 cw(c-374.92,213) 0,233.74 0,-2.48 5334.65,-2.48 5334.65,469.96 cw(c5866.14,440.43) 5895.67,971.93 5895.67,4180.59 cw(c5866.14,4712.09) 5334.65,4682.56 5334.65,5155 0,5155 0,4918.78 cw(c-297.17,4888.49) -206.69,4603.82 -206.69,2576.26 -206.69,548.7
